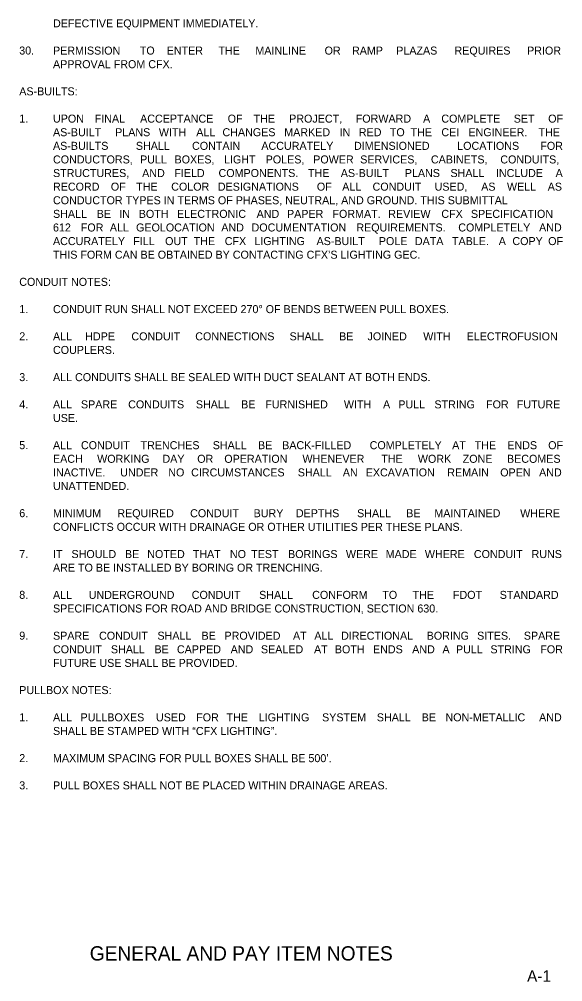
# Model space of a CAD drawing. Extents: x -55 to 2471539, y -90 to 3608906.
# Drawn here: x 1052 to 1526, y -64 to 777 of the extents above; entities that cross this region are included whole.
import ezdxf

# ---------------------------------------------------------------- set-up
doc = ezdxf.new("R2010")
doc.units = 0
for name, color, linetype in [('SheetLines_dp', 7, 'Continuous'), ('TextMisc', 7, 'Continuous'), ('XSCell', 7, 'Continuous')]:
    doc.layers.add(name, color=color, linetype=linetype)

msp = doc.modelspace()

# ---------------------------------------------------------------- texts
at = {"layer": 'SheetLines_dp'}
msp.add_text('A-1', height=10, dxfattribs=at).set_placement((1495.16, -64.49))
at = {"layer": 'TextMisc'}
msp.add_text('GENERAL AND PAY ITEM NOTES ', height=12.5, dxfattribs=at).set_placement((1113.09, -45.92))
at = {"layer": 'XSCell'}
for s, p in [('DEFECTIVE EQUIPMENT IMMEDIATELY.', (1080.99, 770.14)), ('30.', (1051.5, 746.38)), ('PERMISSION ', (1080.99, 746.34)), ('TO ', (1156.84, 746.34)), ('ENTER ', (1180.3, 746.34)), ('THE ', (1225.48, 746.34)), ('MAINLINE ', (1257.78, 746.34)), ('OR ', (1318.26, 746.34)), ('RAMP ', (1342.22, 746.34)), ('PLAZAS ', (1380.82, 746.34)), ('REQUIRES ', (1431.73, 746.34)), ('PRIOR ', (1495.16, 746.34)), ('APPROVAL FROM CFX.', (1080.99, 734.44)), ('AS-BUILTS:', (1051.5, 710.68)), ('1.', (1051.5, 686.88)), ('UPON ', (1080.99, 686.84)), ('FINAL ', (1117.41, 686.84)), ('ACCEPTANCE ', (1157.09, 686.84)), ('OF ', (1233.58, 686.84)), ('THE ', (1256.2, 686.84)), ('PROJECT, ', (1287.31, 686.84)), ('FORWARD ', (1345.45, 686.84)), ('A ', (1404.28, 686.84)), ('COMPLETE ', (1420.22, 686.84)), ('SET ', (1483.47, 686.84)), ('OF ', (1513.59, 686.84)), ('AS-BUILT ', (1080.99, 674.94)), ('PLANS ', (1135.26, 674.94)), ('WITH ', (1173.46, 674.94)), ('ALL ', (1206.16, 674.94)), ('CHANGES ', (1229.03, 674.94)), ('MARKED ', (1283, 674.94)), ('IN ', (1331.35, 674.94)), ('RED ', (1348.18, 674.94)), ('TO ', (1375.25, 674.94)), ('THE ', (1393.35, 674.94)), ('CEI ', (1420.3, 674.94)), ('ENGINEER. ', (1443.89, 674.94)), ('THE ', (1505.1, 674.94)), ('AS-BUILTS ', (1080.99, 663.04)), ('SHALL ', (1153.39, 663.04)), ('CONTAIN ', (1202.46, 663.04)), ('ACCURATELY ', (1263, 663.04)), ('DIMENSIONED ', (1343.94, 663.04)), ('LOCATIONS ', (1434.11, 663.04)), ('FOR ', (1506.71, 663.04)), ('CONDUCTORS, ', (1080.99, 651.14)), ('PULL ', (1157.04, 651.14)), ('BOXES, ', (1187.18, 651.14)), ('LIGHT ', (1230.39, 651.14)), ('POLES, ', (1266.78, 651.14)), ('POWER ', (1308.31, 651.14)), ('SERVICES, ', (1349.37, 651.14)), ('CABINETS, ', (1411.13, 651.14)), ('CONDUITS, ', (1471.76, 651.14)), ('STRUCTURES, ', (1080.99, 639.24)), ('AND ', (1158.87, 639.24)), ('FIELD ', (1186.95, 639.24)), ('COMPONENTS. ', (1225.61, 639.24)), ('THE ', (1303.77, 639.24)), ('AS-BUILT ', (1332.39, 639.24)), ('PLANS ', (1388.33, 639.24)), ('SHALL ', (1428.22, 639.24)), ('INCLUDE ', (1467.92, 639.24)), ('A ', (1520.06, 639.24)), ('RECORD ', (1080.99, 627.34)), ('OF ', (1131.52, 627.34)), ('THE ', (1153.64, 627.34)), ('COLOR ', (1184.25, 627.34)), ('DESIGNATIONS ', (1225, 627.34)), ('OF ', (1311.51, 627.34)), ('ALL ', (1333.62, 627.34)), ('CONDUIT ', (1360.16, 627.34)), ('USED, ', (1414.35, 627.34)), ('AS ', (1455.05, 627.34)), ('WELL ', (1477.57, 627.34)), ('AS ', (1513.18, 627.34)), ('CONDUCTOR TYPES IN TERMS OF PHASES, NEUTRAL, AND GROUND. THIS SUBMITTAL ', (1080.99, 615.44)), ('SHALL ', (1080.99, 603.54)), ('BE ', (1119.17, 603.54)), ('IN ', (1138.91, 603.54)), ('BOTH ', (1155.9, 603.54)), ('ELECTRONIC ', (1189.32, 603.54)), ('AND ', (1258.87, 603.54)), ('PAPER ', (1285.43, 603.54)), ('FORMAT. ', (1325.11, 603.54)), ('REVIEW ', (1373.87, 603.54)), ('CFX ', (1420.25, 603.54)), ('SPECIFICATION ', (1446.08, 603.54)), ('612 ', (1080.99, 591.64)), ('FOR ', (1105.26, 591.64)), ('ALL ', (1130.64, 591.64)), ('GEOLOCATION ', (1153.56, 591.64)), ('AND ', (1227.99, 591.64)), ('DOCUMENTATION ', (1254.44, 591.64)), ('REQUIREMENTS. ', (1345.98, 591.64)), ('COMPLETELY ', (1435.03, 591.64)), ('AND ', (1505.64, 591.64)), ('ACCURATELY ', (1080.99, 579.74)), ('FILL ', (1151.05, 579.74)), ('OUT ', (1178.93, 579.74)), ('THE ', (1203.92, 579.74)), ('CFX ', (1231.04, 579.74)), ('LIGHTING ', (1256.88, 579.74)), ('AS-BUILT ', (1311.22, 579.74)), ('POLE ', (1365.65, 579.74)), ('DATA ', (1397.11, 579.74)), ('TABLE. ', (1429.54, 579.74)), ('A ', (1470.38, 579.74)), ('COPY ', (1482.33, 579.74)), ('OF ', (1513.59, 579.74)), ('THIS FORM CAN BE OBTAINED BY CONTACTING CFX’S LIGHTING GEC.', (1080.99, 567.84)), ('CONDUIT NOTES:', (1051.5, 544.08)), ('1.', (1051.5, 520.28)), ('CONDUIT RUN SHALL NOT EXCEED 270° OF BENDS BETWEEN PULL BOXES.', (1080.99, 520.24)), ('2.', (1051.5, 496.48)), ('ALL ', (1080.99, 496.44)), ('HDPE ', (1109.12, 496.44)), ('CONDUIT ', (1149.48, 496.44)), ('CONNECTIONS ', (1205.26, 496.44)), ('SHALL ', (1287.67, 496.44)), ('BE ', (1330.94, 496.44)), ('JOINED ', (1355.77, 496.44)), ('WITH ', (1404.4, 496.44)), ('ELECTROFUSION ', (1442.34, 496.44)), ('COUPLERS.', (1080.99, 484.54)), ('3.', (1051.5, 460.78)), ('ALL CONDUITS SHALL BE SEALED WITH DUCT SEALANT AT BOTH ENDS.', (1080.99, 460.74)), ('4.', (1051.5, 436.98)), ('ALL ', (1080.99, 436.94)), ('SPARE ', (1105.4, 436.94)), ('CONDUITS ', (1146.66, 436.94)), ('SHALL ', (1205.81, 436.94)), ('BE ', (1245.36, 436.94)), ('FURNISHED ', (1266.47, 436.94)), ('WITH ', (1335.1, 436.94)), ('A ', (1369.33, 436.94)), ('PULL ', (1382.64, 436.94)), ('STRING ', (1414.2, 436.94)), ('FOR ', (1459.3, 436.94)), ('FUTURE ', (1486.16, 436.94)), ('USE.', (1080.99, 425.04)), ('5.', (1051.5, 401.28)), ('ALL ', (1080.99, 401.24)), ('CONDUIT ', (1105.4, 401.24)), ('TRENCHES ', (1157.46, 401.24)), ('SHALL ', (1220.52, 401.24)), ('BE ', (1260.08, 401.24)), ('BACK-FILLED ', (1281.18, 401.24)), ('COMPLETELY ', (1357.62, 401.24)), ('AT ', (1429.7, 401.24)), ('THE ', (1449.39, 401.24)), ('ENDS ', (1477.86, 401.24)), ('OF ', (1513.59, 401.24)), ('EACH ', (1080.99, 389.34)), ('WORKING ', (1119.56, 389.34)), ('DAY ', (1176.58, 389.34)), ('OR ', (1207.01, 389.34)), ('OPERATION ', (1230.64, 389.34)), ('WHENEVER ', (1298.91, 389.34)), ('THE ', (1367.77, 389.34)), ('WORK ', (1399.74, 389.34)), ('ZONE ', (1438.89, 389.34)), ('BECOMES ', (1477.59, 389.34)), ('INACTIVE. ', (1080.99, 377.44)), ('UNDER ', (1139.72, 377.44)), ('NO ', (1181.71, 377.44)), ('CIRCUMSTANCES ', (1201.67, 377.44)), ('SHALL ', (1294.86, 377.44)), ('AN ', (1334.17, 377.44)), ('EXCAVATION ', (1354.17, 377.44)), ('REMAIN ', (1425.41, 377.44)), ('OPEN ', (1471.68, 377.44)), ('AND ', (1505.64, 377.44)), ('UNATTENDED. ', (1080.99, 365.54)), ('6.', (1051.5, 341.78)), ('MINIMUM ', (1080.99, 341.74)), ('REQUIRED ', (1137.17, 341.74)), ('CONDUIT ', (1200.79, 341.74)), ('BURY ', (1256.25, 341.74)), ('DEPTHS ', (1293.15, 341.74)), ('SHALL ', (1346.65, 341.74)), ('BE ', (1389.61, 341.74)), ('MAINTAINED ', (1414.12, 341.74)), ('WHERE ', (1489.11, 341.74)), ('CONFLICTS OCCUR WITH DRAINAGE OR OTHER UTILITIES PER THESE PLANS.', (1080.99, 329.84)), ('7.', (1051.5, 306.08)), ('IT ', (1080.99, 306.04)), ('SHOULD ', (1097.15, 306.04)), ('BE ', (1143.86, 306.04)), ('NOTED ', (1163.32, 306.04)), ('THAT ', (1203.08, 306.04)), ('NO ', (1235.56, 306.04)), ('TEST ', (1254.12, 306.04)), ('BORINGS ', (1286.34, 306.04)), ('WERE ', (1336.87, 306.04)), ('MADE ', (1371.62, 306.04)), ('WHERE ', (1405.84, 306.04)), ('CONDUIT ', (1448.66, 306.04)), ('RUNS ', (1499.08, 306.04)), ('ARE TO BE INSTALLED BY BORING OR TRENCHING. ', (1080.99, 294.14)), ('8.', (1051.5, 270.38)), ('ALL ', (1080.99, 270.34)), ('UNDERGROUND ', (1112.19, 270.34)), ('CONDUIT ', (1202.21, 270.34)), ('SHALL ', (1261.07, 270.34)), ('CONFORM ', (1307.42, 270.34)), ('TO ', (1368.66, 270.34)), ('THE ', (1395.1, 270.34)), ('FDOT ', (1430.37, 270.34)), ('STANDARD ', (1471.21, 270.34)), ('SPECIFICATIONS FOR ROAD AND BRIDGE CONSTRUCTION, SECTION 630.', (1080.99, 258.44)), ('9.', (1051.5, 234.68)), ('SPARE ', (1080.99, 234.64)), ('CONDUIT ', (1121.21, 234.64)), ('SHALL ', (1172.23, 234.64)), ('BE ', (1210.74, 234.64)), ('PROVIDED ', (1230.81, 234.64)), ('AT ', (1290.64, 234.64)), ('ALL ', (1309.28, 234.64)), ('DIRECTIONAL ', (1332.64, 234.64)), ('BORING ', (1407.45, 234.64)), ('SITES. ', (1451.51, 234.64)), ('SPARE ', (1492.31, 234.64)), ('CONDUIT ', (1080.99, 222.74)), ('SHALL ', (1131.57, 222.74)), ('BE ', (1169.63, 222.74)), ('CAPPED ', (1189.25, 222.74)), ('AND ', (1236.18, 222.74)), ('SEALED ', (1262.62, 222.74)), ('AT ', (1309.03, 222.74)), ('BOTH ', (1327.22, 222.74)), ('ENDS ', (1360.52, 222.74)), ('AND ', (1394.76, 222.74)), ('A ', (1421.21, 222.74)), ('PULL ', (1433.03, 222.74)), ('STRING ', (1463.1, 222.74)), ('FOR ', (1506.71, 222.74)), ('FUTURE USE SHALL BE PROVIDED.', (1080.99, 210.84)), ('PULLBOX NOTES:', (1051.5, 187.08)), ('1.', (1051.5, 163.28)), ('ALL ', (1080.99, 163.24)), ('PULLBOXES ', (1105.04, 163.24)), ('USED ', (1170.93, 163.24)), ('FOR ', (1206.08, 163.24)), ('THE ', (1232.58, 163.24)), ('LIGHTING ', (1260.7, 163.24)), ('SYSTEM ', (1316.04, 163.24)), ('SHALL ', (1363.9, 163.24)), ('BE ', (1403.1, 163.24)), ('NON-METALLIC ', (1423.85, 163.24)), ('AND ', (1505.64, 163.24)), ('SHALL BE STAMPED WITH “CFX LIGHTING”.', (1080.99, 151.34)), ('2. ', (1051.5, 127.58)), ('MAXIMUM SPACING FOR PULL BOXES SHALL BE 500’. ', (1080.99, 127.54)), ('3.', (1051.5, 103.78)), ('PULL BOXES SHALL NOT BE PLACED WITHIN DRAINAGE AREAS.', (1080.99, 103.74))]:
    msp.add_text(s, height=7, dxfattribs=at).set_placement(p)

doc.saveas('drawing.dxf')
